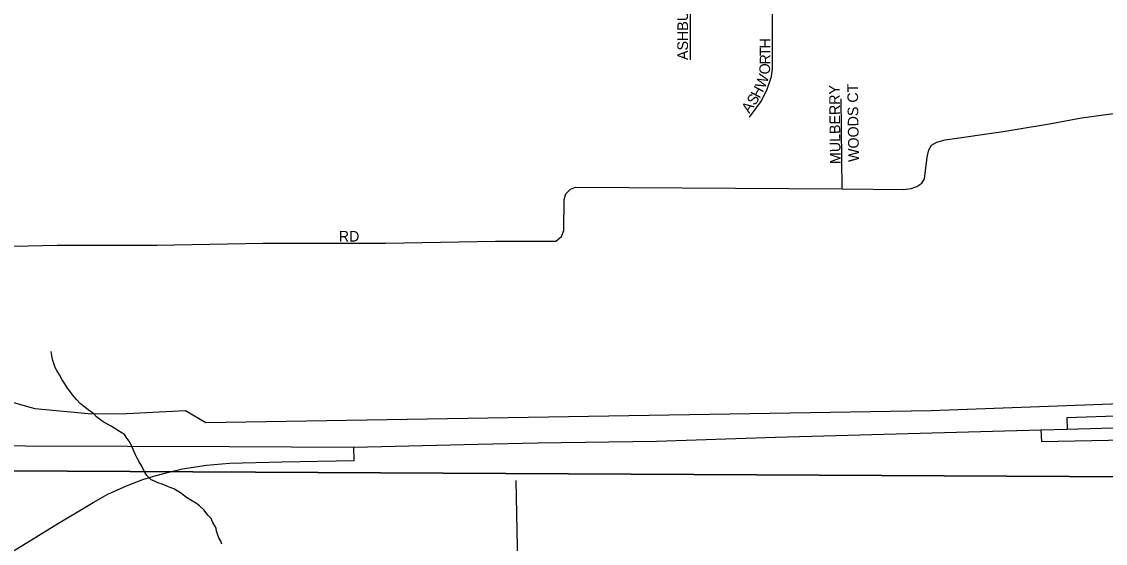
# Model space of a CAD drawing. Extents: x 8.5 to 81.5, y -1.2 to 22.4.
# Drawn here: x 51.227 to 52.191, y 17.778 to 18.242 of the extents above; entities that cross this region are included whole.
import ezdxf

# ---------------------------------------------------------------- set-up
doc = ezdxf.new("R2010")
doc.units = 0
for name, color, linetype in [('GM_X_City_Street', 7, 'Continuous'), ('GM_X_City_Street_Text', 7, 'Continuous'), ('GM_X_Corporation', 7, 'Continuous'), ('GM_X_Interchange_Ramps', 7, 'Continuous'), ('GM_X_Interstate_Route', 7, 'Continuous'), ('GM_X_Minor_River', 7, 'Continuous'), ('GM_X_Section', 7, 'Continuous'), ('GM_X_Township_Subdivision', 7, 'Continuous')]:
    doc.layers.add(name, color=color, linetype=linetype)

msp = doc.modelspace()

# ---------------------------------------------------------------- linework, layer by layer
at = {"layer": 'GM_X_City_Street'}
for points in [[(51.87426, 18.15718), (51.88436, 18.1707), (51.88969, 18.18122), (51.894, 18.19336), (51.89488, 18.20088), (51.895, 18.31833), (51.89464, 18.36054)], [(51.8218, 18.20822), (51.82155, 18.31692)], [(51.95681, 18.0935), (51.95586, 18.17352)], [(52.11425, 18.14686), (52.14133, 18.15126), (52.16968, 18.15651), (52.19835, 18.1605), (52.212, 18.16155)], [(51.19331, 18.04176), (51.2583, 18.04314), (51.34006, 18.04315), (51.34707, 18.04315), (51.44138, 18.04501), (51.5505, 18.04502), (51.64853, 18.04688), (51.70217, 18.04688), (51.70708, 18.05097), (51.70928, 18.05643), (51.70955, 18.08385), (51.71107, 18.08899), (51.71506, 18.09319), (51.71957, 18.09476), (51.95681, 18.0935), (52.01173, 18.09287), (52.01814, 18.09371), (52.02316, 18.09556), (52.0277, 18.09833), (52.03021, 18.10232), (52.03253, 18.12165), (52.03389, 18.12795), (52.0362, 18.13215), (52.04103, 18.13498), (52.04859, 18.13708), (52.09995, 18.14454), (52.11425, 18.14686)]]:
    msp.add_lwpolyline(points, dxfattribs=at)
at = {"layer": 'GM_X_Corporation'}
msp.add_lwpolyline([(51.18389, 17.91338), (51.23521, 17.89888), (51.23857, 17.89794), (51.28925, 17.89333), (51.32027, 17.89342), (51.37266, 17.89617), (51.39061, 17.88565), (52.03616, 17.89606), (52.35682, 17.90797), (52.47232, 17.92622), (52.5475, 17.93012), (52.67256, 18.03874), (52.74213, 18.13444), (52.76437, 18.32277)], dxfattribs=at)
at = {"layer": 'GM_X_Interchange_Ramps'}
for points in [[(52.20849, 17.89138), (52.15686, 17.88973), (52.157, 17.87973)], [(52.13367, 17.87906), (52.13417, 17.86869), (52.20849, 17.87)], [(51.20211, 17.76076), (51.25954, 17.79597), (51.27714, 17.80636), (51.29042, 17.81443), (51.3034, 17.82165), (51.32014, 17.82915), (51.33457, 17.83493), (51.3464, 17.83839), (51.35766, 17.84127), (51.36978, 17.84416), (51.39122, 17.84751), (51.41161, 17.84948), (51.4583, 17.85047), (51.52275, 17.85179), (51.52242, 17.86362)]]:
    msp.add_lwpolyline(points, dxfattribs=at)
at = {"layer": 'GM_X_Interstate_Route'}
for points in [[(51.63265, 17.86616), (51.68579, 17.86738), (51.7916, 17.86878), (51.89753, 17.87235), (52.13367, 17.87906), (52.157, 17.87973), (52.20816, 17.88118), (52.33638, 17.88261), (52.38463, 17.88485)], [(50.94421, 17.86641), (51.06587, 17.86609), (51.16944, 17.86543), (51.23018, 17.86483), (51.41148, 17.86408)], [(51.41148, 17.86408), (51.52242, 17.86362), (51.63265, 17.86616)]]:
    msp.add_lwpolyline(points, dxfattribs=at)
at = {"layer": 'GM_X_Minor_River'}
for points in [[(51.34454, 17.83356), (51.34191, 17.83438), (51.33819, 17.83825), (51.33563, 17.84286), (51.33381, 17.8467), (51.33123, 17.85055), (51.32977, 17.85324), (51.32795, 17.8567), (51.32686, 17.85938), (51.32397, 17.86628), (51.3225, 17.86897), (51.32028, 17.87167), (51.31845, 17.87475), (51.31395, 17.8775), (51.30646, 17.88221), (51.29933, 17.88615), (51.29335, 17.89045), (51.29113, 17.89316), (51.28589, 17.89668), (51.28178, 17.90018), (51.2788, 17.90252), (51.27583, 17.90562), (51.27213, 17.91026), (51.26991, 17.91296), (51.26769, 17.91605), (51.26586, 17.91912), (51.26291, 17.92336), (51.26035, 17.92797), (51.25815, 17.93182), (51.25669, 17.93451), (51.2556, 17.93719), (51.25454, 17.94063), (51.25383, 17.94331), (51.25318, 17.94864)], [(51.40486, 17.77726), (51.40416, 17.77993), (51.40232, 17.78301), (51.40016, 17.78875), (51.39984, 17.79142), (51.39654, 17.79718), (51.39547, 17.80024), (51.39249, 17.80297), (51.38917, 17.80759), (51.38507, 17.81148), (51.38246, 17.81343), (51.37721, 17.81657), (51.37346, 17.81893), (51.36823, 17.82283), (51.36523, 17.82479), (51.36223, 17.82637), (51.35884, 17.82758), (51.35546, 17.82917), (51.3517, 17.83076), (51.34793, 17.83198), (51.34454, 17.83356)]]:
    msp.add_lwpolyline(points, dxfattribs=at)
at = {"layer": 'GM_X_Section'}
for points in [[(52.2136, 18.89831), (52.21491, 17.8371), (51.21175, 17.84266), (51.22018, 18.85778), (51.6895, 18.86113)], [(51.21175, 17.84266), (52.21491, 17.8371), (52.20343, 16.76022), (51.20445, 16.76644)]]:
    msp.add_lwpolyline(points, close=True, dxfattribs=at)
at = {"layer": 'GM_X_Township_Subdivision'}
msp.add_lwpolyline([(51.66589, 17.39907), (51.66677, 17.50389), (51.66823, 17.61639), (51.66822, 17.75998), (51.66674, 17.83398)], dxfattribs=at)

# ---------------------------------------------------------------- texts
at = {"layer": 'GM_X_City_Street_Text'}
for s, rotation, p in [('ASHBURY PL', 90, (51.81967, 18.208)), ('H', 89.99284, (51.89301, 18.21815)), ('T', 89.99561, (51.89301, 18.21148)), ('O', 85.03715, (51.89223, 18.19479)), ('R', 89.8279, (51.89298, 18.20395)), ('W', 69.65358, (51.88785, 18.18193)), ('H', 61.74799, (51.88332, 18.17329)), ('MULBERRY', 90.7465, (51.95551, 18.11548)), ('WOODS CT', 90.79835, (51.97179, 18.11737)), ('S', 56.14679, (51.87909, 18.16689)), ('A', 54.97038, (51.87418, 18.15989)), ('RD', 0.00001, (51.50895, 18.04645))]:
    msp.add_text(s, height=0.00947, rotation=rotation, dxfattribs=at).set_placement(p)

doc.saveas('drawing.dxf')
